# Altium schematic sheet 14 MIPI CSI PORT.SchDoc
size 420 x 297 mm
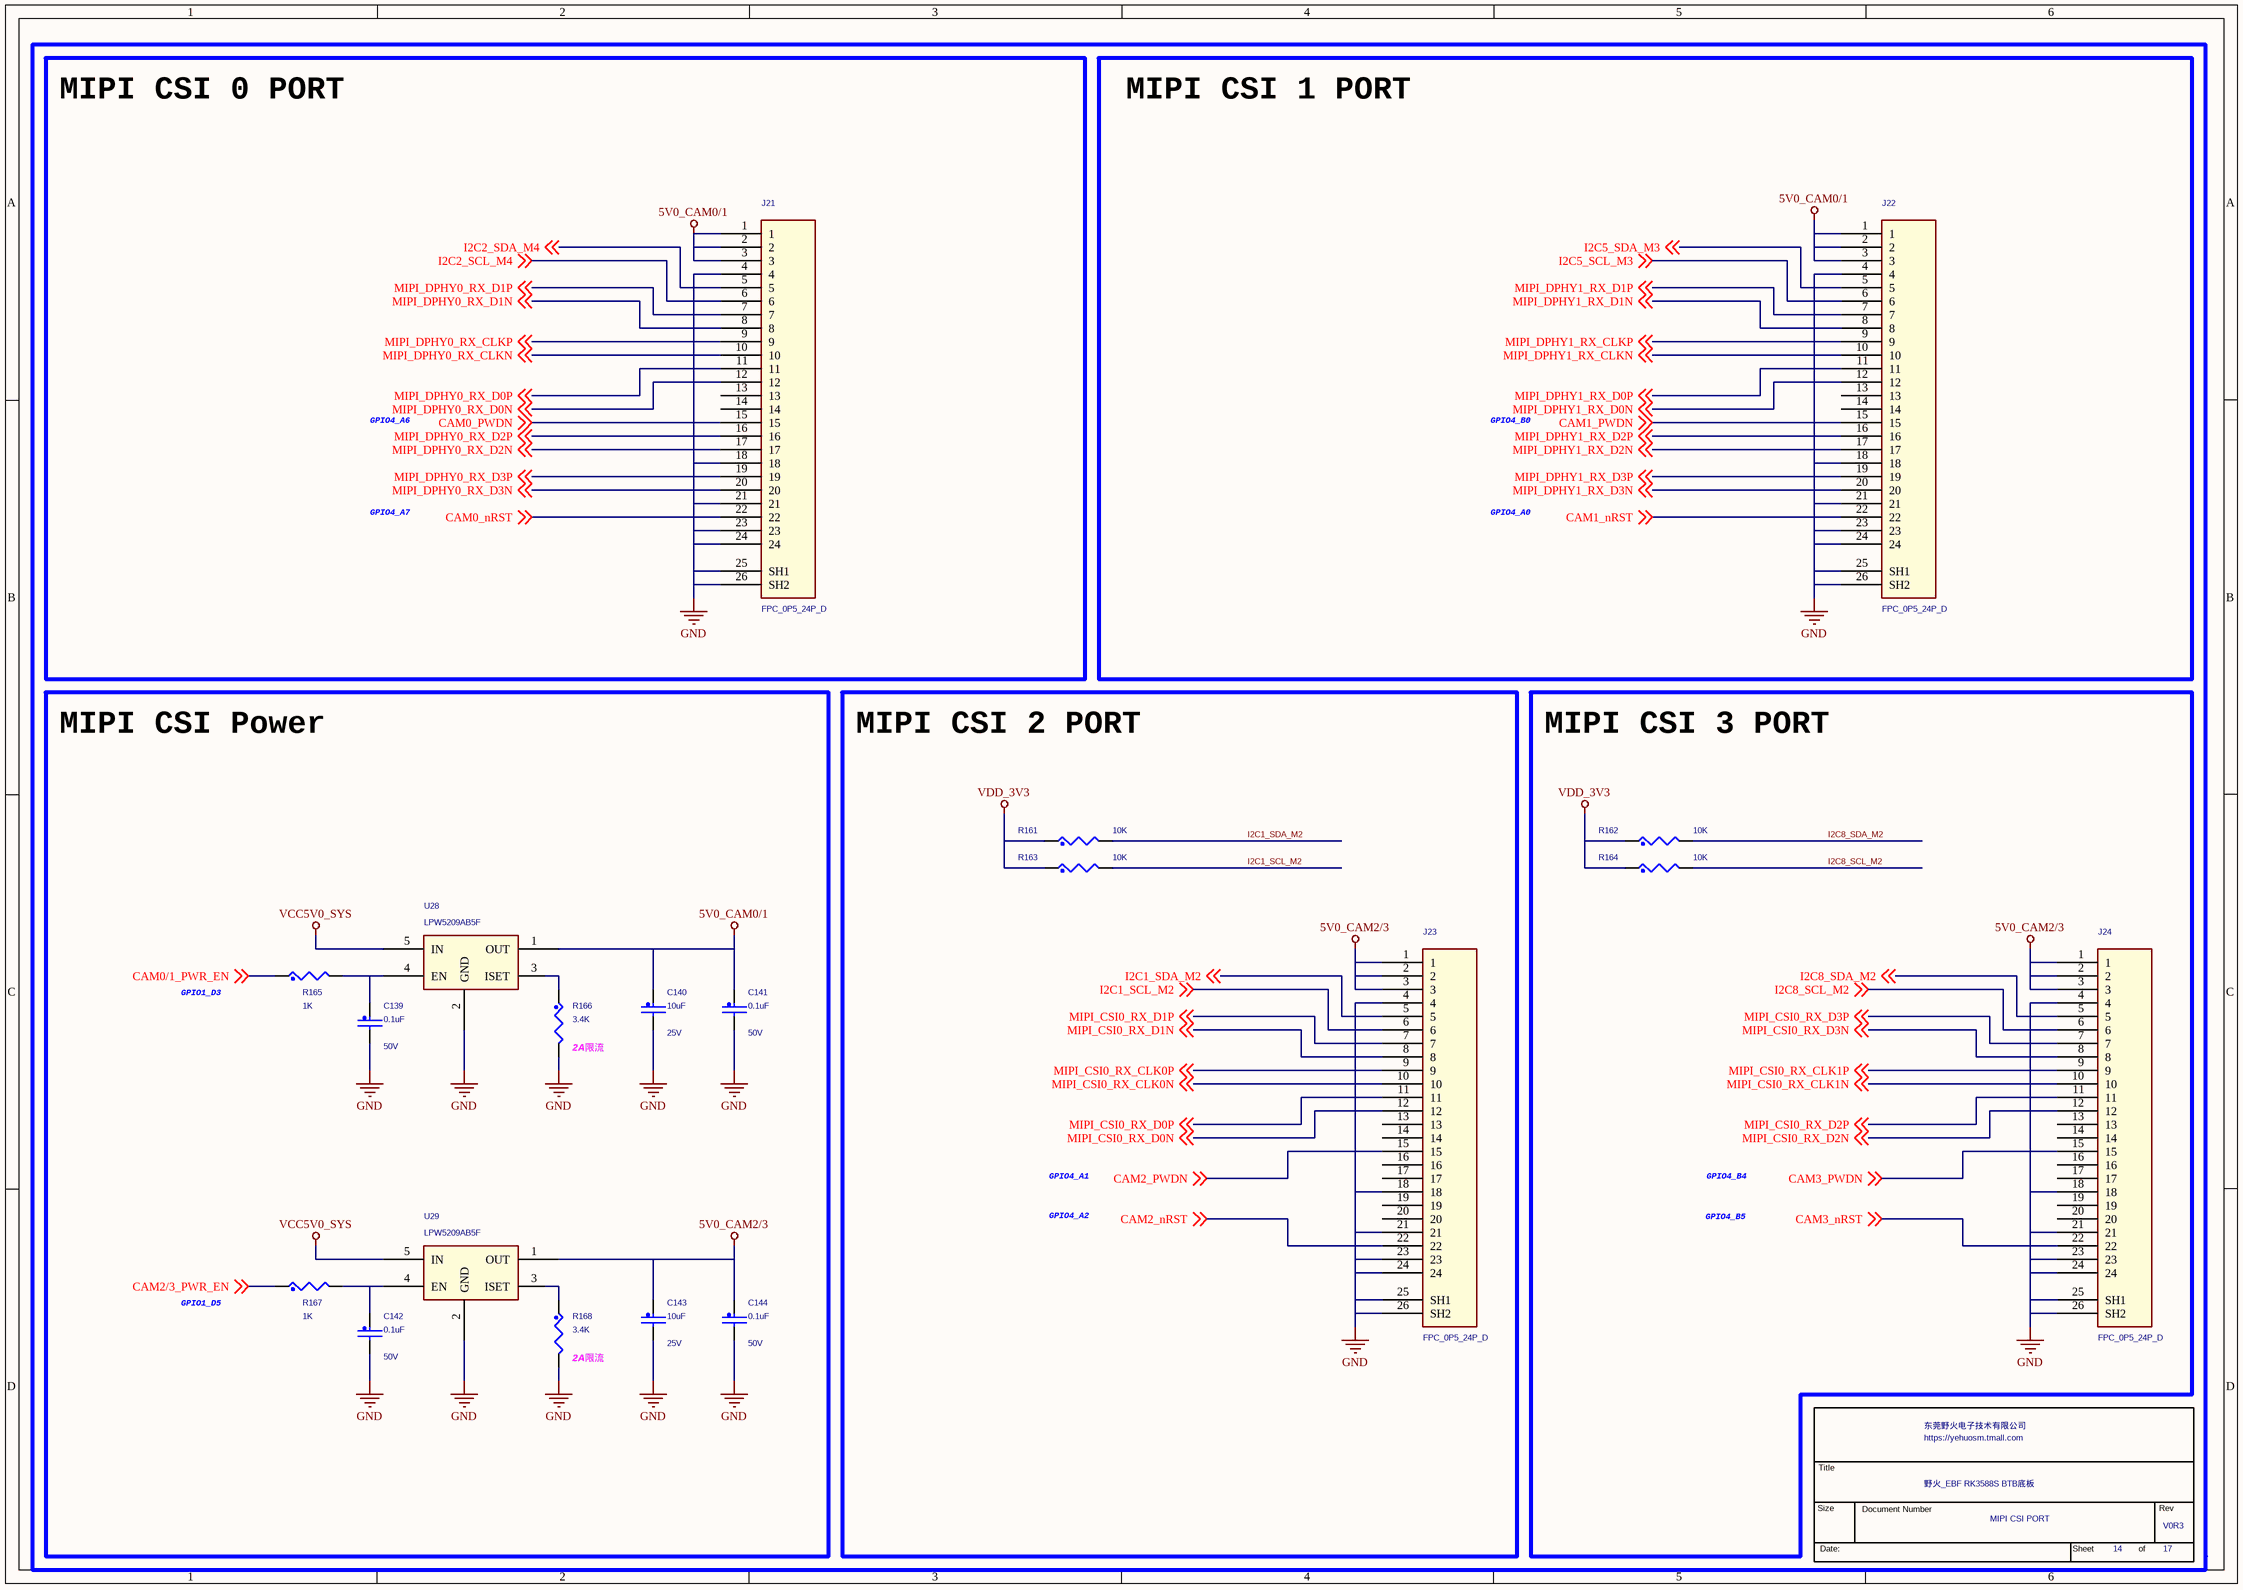
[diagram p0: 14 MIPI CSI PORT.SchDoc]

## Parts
*  Page Count: 17  Page Number: 14  OrgName: 东莞野火电子技术有限公司  Title: 野火_EBF RK3588S BTB底板  RevCode: V0R3  Doc: MIPI CSI PORT  (hidden comment: TitleBlock_YHSCH)  (graphical)
C139  0.1uF  Voltage: 50V  [C0402]
C140  10uF  Voltage: 25V  [C0603]
C141  0.1uF  Voltage: 50V  [C0402]
C142  0.1uF  Voltage: 50V  [C0402]
C143  10uF  Voltage: 25V  [C0603]
C144  0.1uF  Voltage: 50V  [C0402]
J21  FPC_0P5_24P_D  [fpc_24p_0p5]
J22  FPC_0P5_24P_D  [fpc_24p_0p5]
J23  FPC_0P5_24P_D  [fpc_24p_0p5]
J24  FPC_0P5_24P_D  [fpc_24p_0p5]
R161  10K  [R0402]
R162  10K  [R0402]
R163  10K  [R0402]
R164  10K  [R0402]
R165  1K  [R0402]
R166  3.4K  [R0402]
R167  1K  [R0402]
R168  3.4K  [R0402]
U28  LPW5209AB5F  [SOT23-5]
U29  LPW5209AB5F  [SOT23-5]

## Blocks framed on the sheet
MIPI CSI 0 PORT: J21
MIPI CSI 1 PORT: J22
MIPI CSI Power: C139-C144 R165-R168 U28 U29
MIPI CSI 2 PORT: J23 R161 R163
MIPI CSI 3 PORT: J24 R162 R164

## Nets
5V0_CAM0/1: C140.1 C141.1 J21.1 J21.2 J21.3 J22.1 J22.2 J22.3 U28.1(OUT)
5V0_CAM2/3: C143.1 C144.1 J23.1 J23.2 J23.3 J24.1 J24.2 J24.3 U29.1(OUT)
GND: C139.2 C140.2 C141.2 C142.2 C143.2 C144.2 J21.4 J21.18 J21.21 J21.23 J21.24 J21.25(SH1) J21.26(SH2) J22.4 J22.18 J22.21 J22.23 J22.24 J22.25(SH1) J22.26(SH2) J23.4 J23.18 J23.21 J23.23 J23.24 J23.25(SH1) J23.26(SH2) J24.4 J24.18 J24.21 J24.23 J24.24 J24.25(SH1) J24.26(SH2) R166.2 R168.2 U28.2(GND) U29.2(GND)
VCC5V0_SYS: U28.5(IN) U29.5(IN)
VDD_3V3: R161.1 R162.1 R163.1 R164.1
CAM0/1_PWR_EN: R165.1 ; off-sheet CAM0/1_PWR_EN
CAM0_nRST: J21.22 ; off-sheet CAM0_nRST
CAM0_PWDN: J21.15 ; off-sheet CAM0_PWDN
CAM1_nRST: J22.22 ; off-sheet CAM1_nRST
CAM1_PWDN: J22.15 ; off-sheet CAM1_PWDN
CAM2/3_PWR_EN: R167.1 ; off-sheet CAM2/3_PWR_EN
CAM2_nRST: J23.22 ; off-sheet CAM2_nRST
CAM2_PWDN: J23.15 ; off-sheet CAM2_PWDN
CAM3_nRST: J24.22 ; off-sheet CAM3_nRST
CAM3_PWDN: J24.15 ; off-sheet CAM3_PWDN
I2C1_SCL_M2: J23.6 R163.2 ; off-sheet I2C1_SCL_M2
I2C1_SDA_M2: J23.5 R161.2 ; off-sheet I2C1_SDA_M2
I2C2_SCL_M4: J21.6 ; off-sheet I2C2_SCL_M4
I2C2_SDA_M4: J21.5 ; off-sheet I2C2_SDA_M4
I2C5_SCL_M3: J22.6 ; off-sheet I2C5_SCL_M3
I2C5_SDA_M3: J22.5 ; off-sheet I2C5_SDA_M3
I2C8_SCL_M2: J24.6 R164.2 ; off-sheet I2C8_SCL_M2
I2C8_SDA_M2: J24.5 R162.2 ; off-sheet I2C8_SDA_M2
MIPI_CSI0_RX_CLK0N: J23.10 ; off-sheet MIPI_CSI0_RX_CLK0N
MIPI_CSI0_RX_CLK0P: J23.9 ; off-sheet MIPI_CSI0_RX_CLK0P
MIPI_CSI0_RX_CLK1N: J24.10 ; off-sheet MIPI_CSI0_RX_CLK1N
MIPI_CSI0_RX_CLK1P: J24.9 ; off-sheet MIPI_CSI0_RX_CLK1P
MIPI_CSI0_RX_D0N: J23.12 ; off-sheet MIPI_CSI0_RX_D0N
MIPI_CSI0_RX_D0P: J23.11 ; off-sheet MIPI_CSI0_RX_D0P
MIPI_CSI0_RX_D1N: J23.8 ; off-sheet MIPI_CSI0_RX_D1N
MIPI_CSI0_RX_D1P: J23.7 ; off-sheet MIPI_CSI0_RX_D1P
MIPI_CSI0_RX_D2N: J24.12 ; off-sheet MIPI_CSI0_RX_D2N
MIPI_CSI0_RX_D2P: J24.11 ; off-sheet MIPI_CSI0_RX_D2P
MIPI_CSI0_RX_D3N: J24.8 ; off-sheet MIPI_CSI0_RX_D3N
MIPI_CSI0_RX_D3P: J24.7 ; off-sheet MIPI_CSI0_RX_D3P
MIPI_DPHY0_RX_CLKN: J21.10 ; off-sheet MIPI_DPHY0_RX_CLKN
MIPI_DPHY0_RX_CLKP: J21.9 ; off-sheet MIPI_DPHY0_RX_CLKP
MIPI_DPHY0_RX_D0N: J21.12 ; off-sheet MIPI_DPHY0_RX_D0N
MIPI_DPHY0_RX_D0P: J21.11 ; off-sheet MIPI_DPHY0_RX_D0P
MIPI_DPHY0_RX_D1N: J21.8 ; off-sheet MIPI_DPHY0_RX_D1N
MIPI_DPHY0_RX_D1P: J21.7 ; off-sheet MIPI_DPHY0_RX_D1P
MIPI_DPHY0_RX_D2N: J21.17 ; off-sheet MIPI_DPHY0_RX_D2N
MIPI_DPHY0_RX_D2P: J21.16 ; off-sheet MIPI_DPHY0_RX_D2P
MIPI_DPHY0_RX_D3N: J21.20 ; off-sheet MIPI_DPHY0_RX_D3N
MIPI_DPHY0_RX_D3P: J21.19 ; off-sheet MIPI_DPHY0_RX_D3P
MIPI_DPHY1_RX_CLKN: J22.10 ; off-sheet MIPI_DPHY1_RX_CLKN
MIPI_DPHY1_RX_CLKP: J22.9 ; off-sheet MIPI_DPHY1_RX_CLKP
MIPI_DPHY1_RX_D0N: J22.12 ; off-sheet MIPI_DPHY1_RX_D0N
MIPI_DPHY1_RX_D0P: J22.11 ; off-sheet MIPI_DPHY1_RX_D0P
MIPI_DPHY1_RX_D1N: J22.8 ; off-sheet MIPI_DPHY1_RX_D1N
MIPI_DPHY1_RX_D1P: J22.7 ; off-sheet MIPI_DPHY1_RX_D1P
MIPI_DPHY1_RX_D2N: J22.17 ; off-sheet MIPI_DPHY1_RX_D2N
MIPI_DPHY1_RX_D2P: J22.16 ; off-sheet MIPI_DPHY1_RX_D2P
MIPI_DPHY1_RX_D3N: J22.20 ; off-sheet MIPI_DPHY1_RX_D3N
MIPI_DPHY1_RX_D3P: J22.19 ; off-sheet MIPI_DPHY1_RX_D3P
NetC139_1: C139.1 R165.2 U28.4(EN)
NetC142_1: C142.1 R167.2 U29.4(EN)
NetR166_1: R166.1 U28.3(ISET)
NetR168_1: R168.1 U29.3(ISET)

Not connected (* = marked no-connect by the designer): J21 13 14; J22 13 14; J23 13 14 16 17 19 20; J24 13 14 16 17 19 20

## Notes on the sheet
- GPIO4_A6
- GPIO4_B0
- GPIO4_A7
- GPIO4_A0
- GPIO1_D3
- (near R166) 2A限流
- GPIO4_A1
- GPIO4_B4
- GPIO4_A2
- GPIO4_B5
- GPIO1_D5
- (near R168) 2A限流

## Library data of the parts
* = TitleBlock_YHSCH: Cage Code: 1
C139 C142 = CAP_NP: CLASS: DISCRETE; 生命周期: 量产; 价格: 0.029826; 规格书: 风华电容.pdf; 类别: 贴片电容0402; 品牌: 风华; 条码: EBF29060118; 规格编号: 0402X104K500NT; 规格: 贴片电容0.1uF 10% 50V X5R 0402
C140 C143 = CAP_NP: CLASS: DISCRETE; 规格: 贴片电容10uF 20% 25V X5R 0603; 规格编号: CL10A106MA8NRNC; 条码: EBF29060171; 品牌: 三星; 类别: 贴片电容0603; 规格书: 三星电容.pdf; 价格: 0.109811; 生命周期: 量产
C141 C144 = CAP_NP: CLASS: DISCRETE; 规格: 贴片电容0.1uF 10% 50V X5R 0402; 规格编号: 0402X104K500NT; 条码: EBF29060118; 品牌: 风华; 类别: 贴片电容0402; 规格书: 风华电容.pdf; 价格: 0.029826; 生命周期: 量产
J21-J24 = FPC-24P: 规格: FPC连接器 针脚数24 间距0.5mmm 下接 卧贴 翻盖式; 规格编号: AFC01-S24FCA-00; 条码: EBF29040059; 品牌: 钜硕电子; 类别: FPC连接器; 规格书: 钜硕电子-FPC间距0.5mm.pdf; 价格: 0.368739; 生命周期: 量产
R161 R162 = RES: CLASS: DISCRETE; 生命周期: 量产; 价格: 0.002773; 规格书: 厚声-无铅厚膜电阻.pdf; 品牌: 厚声; 规格编号: 0402WGF1002TCE; 类别: 贴片电阻0402; 条码: EBF29070046; 规格: 贴片电阻10K 1% 1/16W 0402
R163 R164 = RES: CLASS: DISCRETE; 生命周期: 量产; 价格: 0.002773; 规格书: 厚声-无铅厚膜电阻.pdf; 品牌: 厚声; 规格编号: 0402WGF1002TCE; 规格: 贴片电阻10K 1% 1/16W 0402; 条码: EBF29070046; 类别: 贴片电阻0402
R165 R167 = RES: CLASS: DISCRETE; 生命周期: 量产; 规格书: 合科泰-RI系列电阻.pdf; 类别: 贴片电阻0402; 品牌: 合科泰; 条码: EBF29070050; 规格编号: RI0402L1001FT; 规格: 贴片电阻1K 1% 1/16W 0402
R166 R168 = RES: CLASS: DISCRETE; 生命周期: 量产; 规格书: 合科泰-RI系列电阻.pdf; 类别: 贴片电阻0402; 品牌: 合科泰; 条码: EBF29070186; 规格编号: RI0402L3401FT; 规格: 贴片电阻3.4K 1% 1/16W 0402
U28 = LPW5209AB5F: 规格: 集成电源开关 导通电阻：80mΩ 最大可设置保护电流：2.1A 输入电压：2.5V~6V 静态电流：30uA 其他功能：软启动、短路保护、热保护; 条码: EBF29280015; 品牌: 微源半导体; 类别: 功率开关; 规格书: 微源半导体_LPW5209AB5F.pdf; 价格: 0.468063; 生命周期: 量产
U29 = LPW5209AB5F: 生命周期: 量产; 价格: 0.468063; 规格书: 微源半导体_LPW5209AB5F.pdf; 类别: 功率开关; 品牌: 微源半导体; 条码: EBF29280015; 规格: 集成电源开关 导通电阻：80mΩ 最大可设置保护电流：2.1A 输入电压：2.5V~6V 静态电流：30uA 其他功能：软启动、短路保护、热保护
